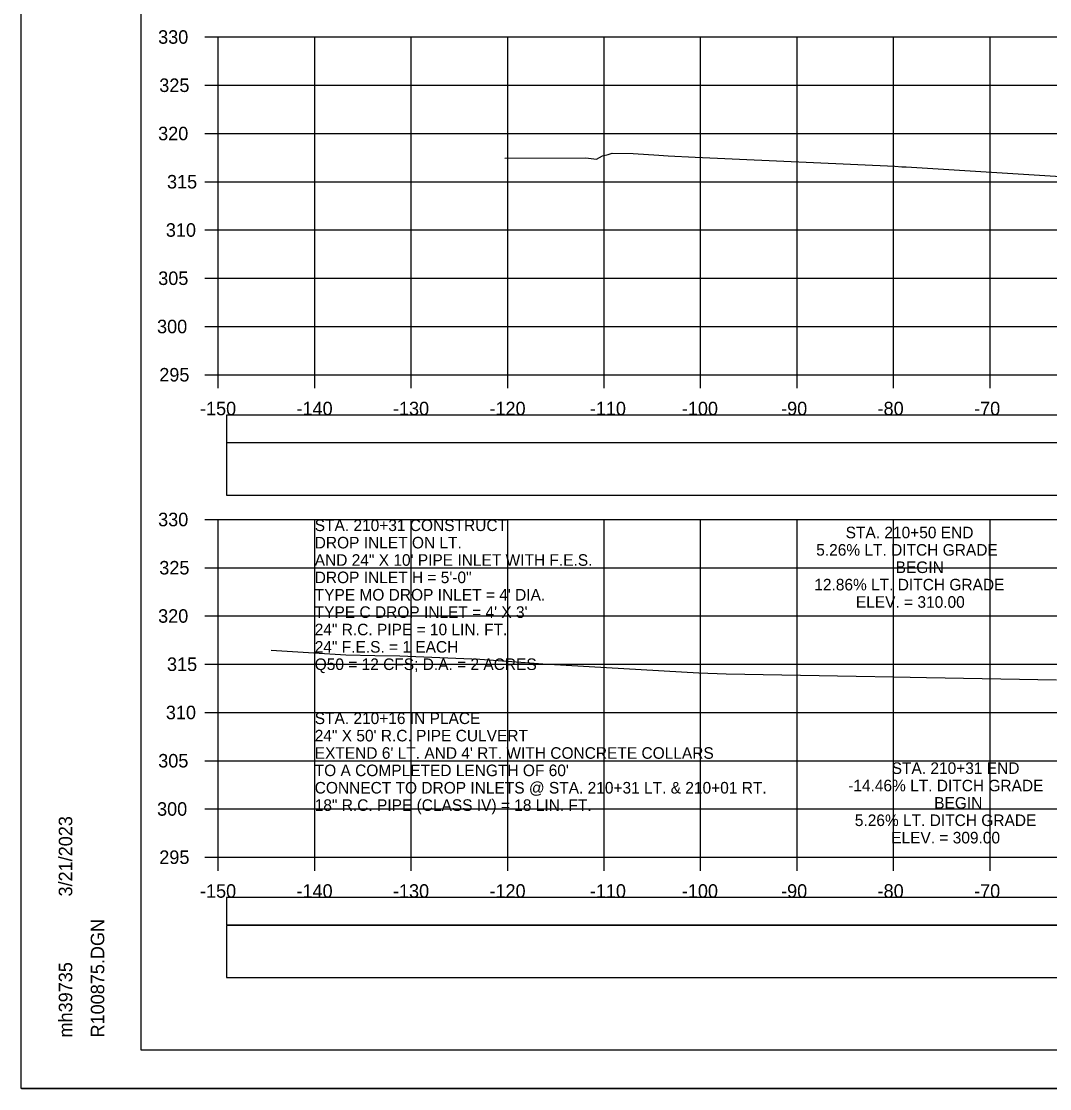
# Model space of a CAD drawing. Extents: x 1368122 to 1710785, y 373130 to 557566.
# Drawn here: x 1369851.8 to 1369958.4, y 375263.7 to 375374.3 of the extents above; entities that cross this region are included whole.
import ezdxf

# ---------------------------------------------------------------- set-up
doc = ezdxf.new("R2010")
doc.units = 0
for name, color, linetype in [('R_Axis', 7, 'Continuous'), ('R_Axis Annot', 7, 'Continuous'), ('R_Border', 7, 'Continuous'), ('R_Exist Surface', 7, 'Continuous'), ('R_Grid', 7, 'Continuous'), ('R_No Plot', 7, 'Continuous'), ('R_Water Annot', 7, 'Continuous'), ('R_Xsect Elev', 7, 'Continuous')]:
    doc.layers.add(name, color=color, linetype=linetype)

msp = doc.modelspace()

# ---------------------------------------------------------------- linework, layer by layer
for points in [[(1369873.09, 375330.68), (1370171.39, 375330.68), (1370171.39, 375333.5), (1369873.09, 375333.5)], [(1369873.09, 375325.21), (1370171.39, 375325.21), (1370171.39, 375330.63), (1369873.09, 375330.63)], [(1369873.09, 375280.68), (1370171.39, 375280.68), (1370171.39, 375283.5), (1369873.09, 375283.5)], [(1369873.09, 375275.21), (1370171.39, 375275.21), (1370171.39, 375280.63), (1369873.09, 375280.63)]]:
    msp.add_lwpolyline(points, close=True)
at = {"layer": 'R_Axis'}
for p, q in [((1369870.84, 375372.69), (1369872.24, 375372.69)), ((1369872.24, 375337.69), (1369872.24, 375372.69)), ((1369870.84, 375367.69), (1369872.24, 375367.69)), ((1369870.84, 375362.69), (1369872.24, 375362.69)), ((1369870.84, 375357.69), (1369872.24, 375357.69)), ((1369870.84, 375352.69), (1369872.24, 375352.69)), ((1369870.84, 375347.69), (1369872.24, 375347.69)), ((1369870.84, 375342.69), (1369872.24, 375342.69)), ((1369870.84, 375337.69), (1369872.24, 375337.69)), ((1369872.24, 375337.69), (1370172.24, 375337.69)), ((1369872.24, 375336.29), (1369872.24, 375337.69)), ((1369882.24, 375336.29), (1369882.24, 375337.69)), ((1369892.24, 375336.29), (1369892.24, 375337.69)), ((1369902.24, 375336.29), (1369902.24, 375337.69)), ((1369912.24, 375336.29), (1369912.24, 375337.69)), ((1369922.24, 375336.29), (1369922.24, 375337.69)), ((1369932.24, 375336.29), (1369932.24, 375337.69)), ((1369942.24, 375336.29), (1369942.24, 375337.69)), ((1369952.24, 375336.29), (1369952.24, 375337.69)), ((1369870.84, 375322.69), (1369872.24, 375322.69)), ((1369872.24, 375287.69), (1369872.24, 375322.69)), ((1369870.84, 375317.69), (1369872.24, 375317.69)), ((1369870.84, 375312.69), (1369872.24, 375312.69)), ((1369870.84, 375307.69), (1369872.24, 375307.69)), ((1369870.84, 375302.69), (1369872.24, 375302.69)), ((1369870.84, 375297.69), (1369872.24, 375297.69)), ((1369870.84, 375292.69), (1369872.24, 375292.69)), ((1369870.84, 375287.69), (1369872.24, 375287.69)), ((1369872.24, 375287.69), (1370172.24, 375287.69)), ((1369872.24, 375286.29), (1369872.24, 375287.69)), ((1369882.24, 375286.29), (1369882.24, 375287.69)), ((1369892.24, 375286.29), (1369892.24, 375287.69)), ((1369902.24, 375286.29), (1369902.24, 375287.69)), ((1369912.24, 375286.29), (1369912.24, 375287.69)), ((1369922.24, 375286.29), (1369922.24, 375287.69)), ((1369932.24, 375286.29), (1369932.24, 375287.69)), ((1369942.24, 375286.29), (1369942.24, 375287.69)), ((1369952.24, 375286.29), (1369952.24, 375287.69))]:
    msp.add_line(p, q, dxfattribs=at)
at = {"layer": 'R_Border'}
for p, q in [((1369864.24, 375267.69), (1369864.24, 375473.15)), ((1369864.24, 375267.69), (1369864.24, 375267.69)), ((1370180.42, 375267.69), (1369864.24, 375267.69))]:
    msp.add_line(p, q, dxfattribs=at)
at = {"layer": 'R_Exist Surface'}
for points in [[(1369901.93, 375360.14), (1369910.34, 375360.18), (1369911.46, 375360.04), (1369912.07, 375360.36), (1369912.66, 375360.52), (1369913.06, 375360.66), (1369915.23, 375360.61), (1369917.91, 375360.44), (1369918.88, 375360.36), (1369921.66, 375360.25), (1369942.37, 375359.29), (1369943.08, 375359.24), (1369943.55, 375359.24), (1369966.76, 375357.77)], [(1369877.73, 375309.16), (1369885.45, 375308.66), (1369888.48, 375308.59), (1369891.06, 375308.57), (1369899.36, 375308.2), (1369903.59, 375307.9), (1369905.87, 375307.74), (1369906.51, 375307.69), (1369922.07, 375306.8), (1369924.88, 375306.69), (1369938.37, 375306.44), (1369942.26, 375306.37), (1369945.66, 375306.31), (1369959.11, 375306.07)]]:
    msp.add_lwpolyline(points, dxfattribs=at)
at = {"layer": 'R_Grid'}
for p, q in [((1369872.24, 375372.69), (1370172.24, 375372.69)), ((1369872.24, 375337.69), (1369872.24, 375372.69)), ((1369882.24, 375337.69), (1369882.24, 375372.69)), ((1369892.24, 375337.69), (1369892.24, 375372.69)), ((1369902.24, 375337.69), (1369902.24, 375372.69)), ((1369912.24, 375337.69), (1369912.24, 375372.69)), ((1369922.24, 375337.69), (1369922.24, 375372.69)), ((1369932.24, 375337.69), (1369932.24, 375372.69)), ((1369942.24, 375337.69), (1369942.24, 375372.69)), ((1369952.24, 375337.69), (1369952.24, 375372.69)), ((1369872.24, 375367.69), (1370172.24, 375367.69)), ((1369872.24, 375362.69), (1370172.24, 375362.69)), ((1369872.24, 375357.69), (1370172.24, 375357.69)), ((1369872.24, 375352.69), (1370172.24, 375352.69)), ((1369872.24, 375347.69), (1370172.24, 375347.69)), ((1369872.24, 375342.69), (1370172.24, 375342.69)), ((1369872.24, 375337.69), (1370172.24, 375337.69)), ((1369872.24, 375322.69), (1370172.24, 375322.69)), ((1369872.24, 375287.69), (1369872.24, 375322.69)), ((1369882.24, 375287.69), (1369882.24, 375322.69)), ((1369892.24, 375287.69), (1369892.24, 375322.69)), ((1369902.24, 375287.69), (1369902.24, 375322.69)), ((1369912.24, 375287.69), (1369912.24, 375322.69)), ((1369922.24, 375287.69), (1369922.24, 375322.69)), ((1369932.24, 375287.69), (1369932.24, 375322.69)), ((1369942.24, 375287.69), (1369942.24, 375322.69)), ((1369952.24, 375287.69), (1369952.24, 375322.69)), ((1369872.24, 375317.69), (1370172.24, 375317.69)), ((1369872.24, 375312.69), (1370172.24, 375312.69)), ((1369872.24, 375307.69), (1370172.24, 375307.69)), ((1369872.24, 375302.69), (1370172.24, 375302.69)), ((1369872.24, 375297.69), (1370172.24, 375297.69)), ((1369872.24, 375292.69), (1370172.24, 375292.69)), ((1369872.24, 375287.69), (1370172.24, 375287.69))]:
    msp.add_line(p, q, dxfattribs=at)
at = {"layer": 'R_No Plot'}
msp.add_line((1369851.84, 375263.71), (1370185.17, 375263.71), dxfattribs=at)
for points in [[(1369851.83, 375477.04), (1370185.17, 375477.04), (1370185.17, 375263.71), (1369851.83, 375263.71)], [(1370098.16, 375473.15), (1370117.78, 375473.15), (1370117.78, 375463.27), (1370133.89, 375463.27), (1370157.09, 375463.27), (1370157.21, 375435.11), (1370180.42, 375435.11), (1370180.42, 375267.69), (1369864.24, 375267.69), (1369864.24, 375473.15)]]:
    msp.add_lwpolyline(points, close=True, dxfattribs=at)

# ---------------------------------------------------------------- texts
at = {"layer": 'R_Axis Annot'}
for s, p in [('330', (1369866.01, 375371.99)), ('325', (1369866.13, 375366.99)), ('320', (1369866.01, 375361.99)), ('315', (1369866.93, 375356.99)), ('310', (1369866.81, 375351.99)), ('305', (1369866.02, 375346.99)), ('300', (1369865.9, 375341.99)), ('295', (1369866.13, 375336.99)), ('-150', (1369870.35, 375333.49)), ('-140', (1369880.35, 375333.49)), ('-130', (1369890.35, 375333.49)), ('-120', (1369900.35, 375333.49)), ('-110', (1369910.75, 375333.49)), ('-100', (1369920.29, 375333.49)), ('-90', (1369930.58, 375333.49)), ('-80', (1369940.58, 375333.49)), ('-70', (1369950.58, 375333.49)), ('330', (1369866.01, 375321.99)), ('325', (1369866.13, 375316.99)), ('320', (1369866.01, 375311.99)), ('315', (1369866.93, 375306.99)), ('310', (1369866.81, 375301.99)), ('305', (1369866.02, 375296.99)), ('300', (1369865.9, 375291.99)), ('295', (1369866.13, 375286.99)), ('-150', (1369870.35, 375283.49)), ('-140', (1369880.35, 375283.49)), ('-130', (1369890.35, 375283.49)), ('-120', (1369900.35, 375283.49)), ('-110', (1369910.75, 375283.49)), ('-100', (1369920.29, 375283.49)), ('-90', (1369930.58, 375283.49)), ('-80', (1369940.58, 375283.49)), ('-70', (1369950.58, 375283.49))]:
    msp.add_text(s, height=1.4, dxfattribs=at).set_placement(p)
at = {"layer": 'R_Border'}
for s, p in [('3/21/2023', (1369857.11, 375283.62)), ('R100875.DGN', (1369860.43, 375269.01)), ('mh39735', (1369857.11, 375269.01))]:
    msp.add_text(s, height=1.4, rotation=90, dxfattribs=at).set_placement(p)
at = {"layer": 'R_Water Annot'}
for s, p in [('STA. 210+31 CONSTRUCT', (1369882.24, 375321.49)), ('DROP INLET ON LT.', (1369882.24, 375319.69)), ('AND 24" X 10\' PIPE INLET WITH F.E.S.', (1369882.24, 375317.89)), ('DROP INLET H = 5\'-0"', (1369882.24, 375316.09)), ("TYPE MO DROP INLET = 4' DIA.", (1369882.24, 375314.29)), ("TYPE C DROP INLET = 4' X 3'", (1369882.24, 375312.49)), ('24" R.C. PIPE = 10 LIN. FT.', (1369882.24, 375310.69)), ('24" F.E.S. = 1 EACH', (1369882.24, 375308.89)), ('Q50 = 12 CFS; D.A. = 2 ACRES', (1369882.24, 375307.09)), ('STA. 210+16 IN PLACE', (1369882.24, 375301.49)), ('24" X 50\' R.C. PIPE CULVERT', (1369882.24, 375299.69)), ("EXTEND 6' LT. AND 4' RT. WITH CONCRETE COLLARS", (1369882.24, 375297.89)), ("TO A COMPLETED LENGTH OF 60'", (1369882.24, 375296.09)), ('CONNECT TO DROP INLETS @ STA. 210+31 LT. & 210+01 RT.', (1369882.24, 375294.29)), ('18" R.C. PIPE (CLASS IV) = 18 LIN. FT.', (1369882.24, 375292.49))]:
    msp.add_text(s, height=1.2, dxfattribs=at).set_placement(p)
at = {"layer": 'R_Xsect Elev'}
for s, p in [('STA. 210+50 END', (1369937.27, 375320.74)), ('5.26% LT. DITCH GRADE', (1369934.22, 375318.94)), ('BEGIN', (1369942.45, 375317.14)), ('12.86% LT. DITCH GRADE', (1369934.02, 375315.34)), ('ELEV. = 310.00', (1369938.33, 375313.54)), ('STA. 210+31 END', (1369942.04, 375296.32)), ('-14.46% LT. DITCH GRADE', (1369937.53, 375294.52)), ('BEGIN', (1369946.45, 375292.72)), ('5.26% LT. DITCH GRADE', (1369938.22, 375290.92)), ('ELEV. = 309.00', (1369941.99, 375289.12))]:
    msp.add_text(s, height=1.2, dxfattribs=at).set_placement(p)

doc.saveas('drawing.dxf')
